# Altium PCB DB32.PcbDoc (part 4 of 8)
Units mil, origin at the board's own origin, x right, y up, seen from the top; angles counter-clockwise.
Board outline 3236.22 x 4456.69 mil, 8 copper layers (Top Layer, MidLayer1, MidLayer2, GND-Layer5, MidLayer3, VCC, MidLayer4, Bottom Layer), stack 61.8 mil thick; 207 components, 474 nets, 1777 pads, 1474 vias.
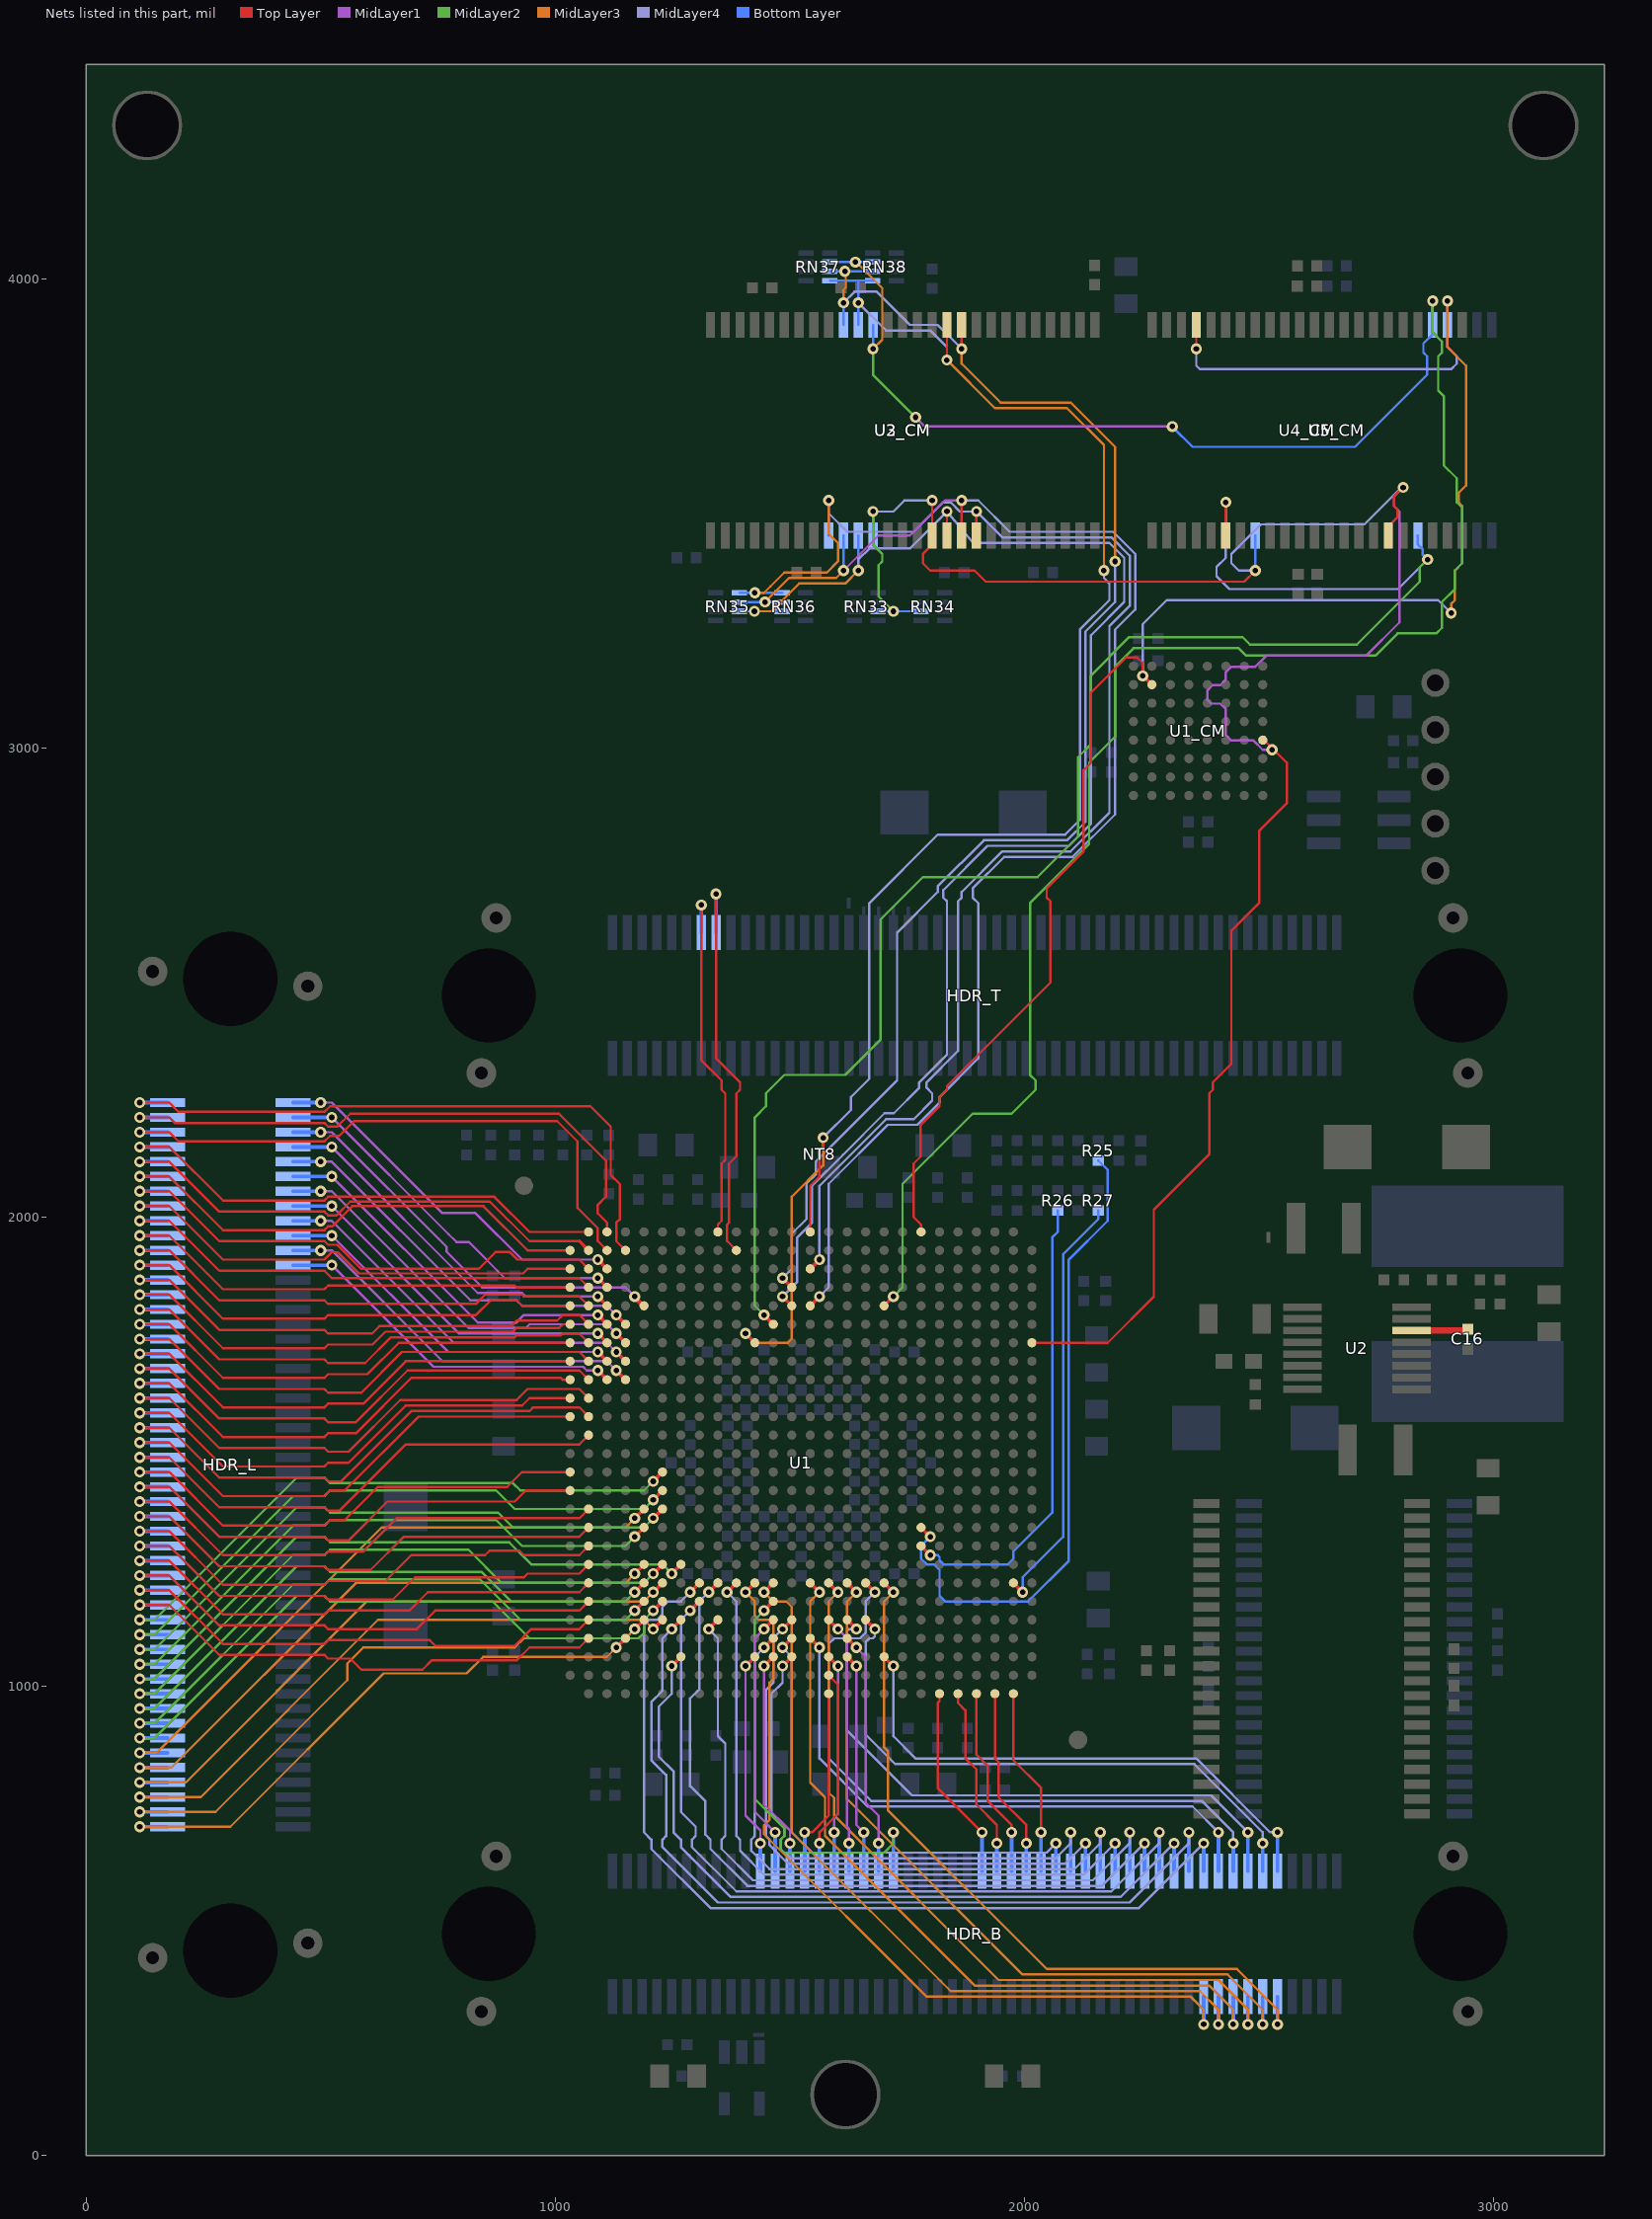
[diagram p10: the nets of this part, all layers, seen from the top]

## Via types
v1: diameter 23.62, hole 11.81, Top Layer to Bottom Layer, 839 vias
v2: diameter 23.62, hole 11.81, Top Layer to Bottom Layer, tented both sides, 499 vias
v3: diameter 27.56, hole 15.75, Top Layer to Bottom Layer, 135 vias
v4: diameter 23.62, hole 11.81, Top Layer to Bottom Layer, tented top, 1 vias

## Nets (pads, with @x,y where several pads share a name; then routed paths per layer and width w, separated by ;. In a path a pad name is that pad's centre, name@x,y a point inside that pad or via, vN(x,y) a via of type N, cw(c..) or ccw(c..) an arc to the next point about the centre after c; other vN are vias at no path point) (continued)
BUS_NBE3: RN37.6 RN38.7 U1.E18 U3_CM.39 U5_CM.40 | length 5006.7
  Top Layer w7.87: U1.E18@1700.79,1811.02 v1(1720.47,1830.71)
  MidLayer1 w5: v2(1767.72,3704.72) 1787.4,3685.04 v2(2314.96,3685.04)
  MidLayer2 w5: v2(1677.17,3850.39) 1677.17,3795.28 v2(1767.72,3704.72) ; v1(1720.47,1830.71) 1740.16,1850.39 1740.16,2031.5 1740.16,2039.37 1740.16,2070.86 1889.76,2220.47 1972.44,2220.47 2023.62,2271.65 2023.62,2291.34 2011.81,2303.15 2011.81,2669.29 2137.8,2795.28 2137.8,2968.5 2192.91,3023.62 2192.91,3173.23 2232.28,3212.6 2456.69,3212.6 2472.44,3196.85 2748.03,3196.85 2795.28,3244.1 2877.95,3244.1 2889.76,3255.91 2889.76,3311.02 2917.32,3338.58 2917.32,3377.95 2933.07,3393.7 2933.07,3511.81 2921.26,3523.62 2921.26,3574.8 2893.7,3602.36 2893.7,3750 2881.89,3761.81 2881.89,3834.65 2889.76,3842.52 2889.76,3866.14 2870.08,3885.83 v2(2870.08,3952.76)
  MidLayer3 w5: v1@1641.54,4035.43 1696.85,3980.12 1696.85,3870.08 v2(1677.17,3850.39)
  Bottom Layer w5: RN37.6@1586.22,4035.43 v1(1639.78,4035.43) RN38.7@1676.19,4035.43 RN38.7@1677.56,4035.43 ; v2(1677.17,3850.39) U3_CM.39@1677.17,3901.57 ; v2(2314.96,3685.04) 2358.27,3641.73 2704.72,3641.73 2858.27,3795.28 2858.27,3834.65 2850.39,3842.52 2850.39,3862.2 2870.08,3881.89 U5_CM.40@2870.08,3901.57 v2(2870.08,3952.76)
BUS_NOE: U1.A20 U1_CM.G2 U4_CM.41 U5_CM.41 | length 3868.3
  Top Layer w5: U1.A20@1779.53,1968.5 1779.53,1984.25 1763.78,2000 1763.78,2031.5 1763.78,2043.31 1763.78,2114.17 1778.54,2128.94 1778.54,2195.87 1818.9,2236.22 1818.9,2255.91 1834.64,2271.65 1834.64,2279.53 2055.12,2500 2055.12,2673.23 2047.24,2681.1 2047.24,2700.79 2125.98,2779.53 2125.98,2952.76 2141.73,2968.5 2141.73,3118.11 2216.54,3192.91 2240.16,3192.91 2251.97,3181.1 v1@2251.97,3154.53 ; v1@2255.91,3150.59 2255.91,3153.54 v1@2255.91,3154.53 ; v2(2366.14,3850.39) U4_CM.41@2366.14,3901.57
  Top Layer w7.87: v1@2251.97,3154.53 2252.46,3154.04 2255.91,3150.59 U1_CM.G2@2271.65,3134.84
  MidLayer3 w5: v2(2901.58,3952.76) 2901.57,3854.33 2940.94,3814.96 2940.94,3559.06 2925.2,3543.31 2925.2,3523.62 2933.07,3515.75 2933.07,3393.7 2917.32,3377.95 2917.32,3314.96 2909.45,3307.09 v1(2909.45,3287.4)
  MidLayer4 w5: v1(2251.97,3153.54) 2251.97,3263.78 2303.15,3314.96 2881.89,3314.96 v1(2909.45,3287.4) ; v2(2366.14,3850.39) 2366.14,3814.96 2374.02,3807.09 2909.45,3807.09 2921.26,3818.9 2921.26,3834.65 2901.58,3854.33 v2(2901.58,3952.76)
  Bottom Layer w5: U5_CM.41@2901.57,3901.57 v2(2901.58,3952.76)
BUS_NWE: RN33.7 RN34.6 U1.G26 U1_CM.A5 U2_CM.16 U3_CM.16 U4_CM.17 U5_CM.17 | length 4738.4
  Top Layer w5: U2_CM.16@1803.14,3452.75 v2(1803.14,3527.55) ; U2_CM.16@1803.15,3460.62 U2_CM.16@1803.15,3452.76 1803.15,3433.07 1783.46,3413.39 1783.46,3393.7 1799.21,3377.95 1893.7,3377.95 1917.32,3354.33 2468.5,3354.33 v1(2492.13,3377.95) ; U1.G26@2015.75,1732.28 2078.74,1732.28 2090.55,1732.28 2177.17,1732.28 2275.59,1830.71 2275.59,2015.75 2393.7,2133.86 2393.7,2263.78 2401.57,2271.65 2401.57,2287.4 2440.94,2326.77 2440.94,2610.24 2500,2669.29 2500,2822.83 2559.06,2881.89 2559.06,2968.5 2529.53,2998.03 2510.82,3016.74 U1_CM.A5@2507.87,3016.73 ; U4_CM.17@2775.59,3452.76 2775.59,3472.44 2795.28,3492.13 2795.28,3507.87 2787.4,3515.75 2787.4,3535.43 v1(2807.09,3555.12)
  MidLayer1 w5: v1(2527.56,2996.06) 2507.87,2996.06 2488.19,3015.75 2440.94,3015.75 2429.13,3027.56 2429.13,3082.68 2417.32,3094.49 2397.64,3094.49 2389.76,3102.36 2389.76,3122.05 2401.57,3133.86 2417.32,3133.86 2429.13,3145.67 2429.13,3161.42 2440.94,3173.23 2492.13,3173.23 2515.75,3196.85 2728.35,3196.85 2799.21,3267.72 2799.21,3503.94 2787.4,3515.75 2787.4,3535.43 v1(2807.09,3555.12)
  MidLayer2 w5: v2(1677.17,3503.94) 1677.17,3433.07 1696.85,3413.39 1696.85,3397.64 1688.98,3389.76 1688.98,3322.83 v1(1720.47,3291.34)
  MidLayer4 w5: v2(1677.17,3503.94) 1720.47,3503.94 1744.09,3527.55 v2(1803.14,3527.55) ; v1(2492.13,3377.95) 2456.69,3377.95 2440.94,3393.7 2440.94,3413.39 2503.94,3476.38 2724.41,3476.38 v1@2805.12,3557.09
  Bottom Layer w5: U3_CM.16@1677.17,3452.76 v2(1677.17,3503.94) ; RN33.7@1688.18,3291.34 v1(1720.47,3291.34) RN34.6@1779.53,3291.34 RN34.6@1779.92,3291.34 ; v1(2492.13,3377.95) U5_CM.17@2492.13,3452.76
BUS_SDRAM_CKE: RN37.7 RN38.6 U1.D13 U2_CM.37 U3_CM.37 | length 3199.4
  Top Layer w5: v2(1866.14,3850.39) U2_CM.37@1866.14,3901.57
  Top Layer w7.87: v1(1484.25,1870.08) U1.D13@1503.94,1850.39
  MidLayer3 w5: v2(1614.17,3948.82) 1614.17,3976.38 1618.9,3981.11 v1@1618.9,4015.75 ; v2(1866.14,3850.39) 1866.14,3818.9 1948.82,3736.22 2098.43,3736.22 2192.91,3641.73 v1(2192.91,3397.64)
  MidLayer4 w5: v1(1484.25,1870.08) 1503.94,1889.76 1503.94,1964.57 1535.43,1996.06 1535.43,2031.5 1535.43,2043.31 1535.43,2070.87 1555.12,2090.55 1555.12,2118.11 1728.35,2291.34 1728.35,2606.3 1814.96,2692.91 1814.96,2704.72 1913.39,2803.15 2090.55,2803.15 2129.92,2842.52 2129.92,3248.03 2192.91,3311.02 v1(2192.91,3397.64) ; v2(1614.17,3948.82) 1637.8,3972.44 1685.04,3972.44 1755.91,3901.57 1814.96,3901.57 v2(1866.14,3850.39)
  Bottom Layer w5: RN37.7@1586.22,4015.75 v1(1617.14,4015.75) RN38.6@1676.19,4015.75 RN38.6@1677.56,4015.75 ; U3_CM.37@1614.17,3901.57 v2(1614.17,3948.82)
BUS_SDRAM_CLK: NT8.2 RN37.8 RN38.5 U1.G11 U2_CM.38 U3_CM.38 | length 3444.5
  Top Layer w5: NT8.2@1562.99,2141.73 1570.87,2149.61 v1(1570.87,2169.29) ; v2(1834.64,3826.77) U2_CM.38@1834.65,3901.57
  Top Layer w7.87: v1(1405.51,1751.97) U1.G11@1425.2,1732.28
  MidLayer3 w5: v1(1405.51,1751.97) 1425.2,1732.28 1496.06,1732.28 1503.94,1740.16 1503.94,2043.31 1570.87,2110.24 v1(1570.87,2169.29) ; v2(1834.64,3826.77) 1937,3724.41 2090.55,3724.41 2169.29,3645.67 v1(2169.29,3377.95)
  MidLayer4 w5: v1(1570.87,2169.29) 1629.92,2228.35 1629.92,2255.91 1669.29,2295.28 1669.29,2669.29 1814.96,2814.96 2086.61,2814.96 2118.11,2846.46 2118.11,3251.97 2181.1,3314.96 2181.1,3350.39 2169.29,3362.2 v1(2169.29,3377.95) ; v2(1645.67,3948.82) 1704.72,3889.76 1799.21,3889.76 1834.64,3854.34 v2(1834.64,3826.77)
  Bottom Layer w5: RN37.8@1586.22,3996.06 RN38.5@1676.19,3996.06 RN38.5@1677.56,3996.06 ; U3_CM.38@1645.67,3901.57 v2(1645.67,3948.82) 1645.67,3996.06
BUS_SDRAM_FEEDBACK: NT8.1 U1.A14 | length 165.6
  Top Layer w5: U1.A14@1543.31,1968.5 1543.31,2066.93 1562.99,2086.61 NT8.1@1562.99,2125.98
BUS_SDRAM_NCAS: RN35.7 RN36.6 U1.E13 U2_CM.17 U3_CM.17 | length 3175.8
  Top Layer w5: U2_CM.17@1834.65,3452.76 1834.64,3499.99 v1(1834.65,3503.94)
  Top Layer w7.87: v1(1484.25,1830.71) U1.E13@1503.94,1811.02
  MidLayer3 w5: v1(1424.23,3291.34) 1460.63,3291.34 1519.68,3350.39 1618.11,3350.39 v2(1645.67,3377.95)
  MidLayer4 w5: v1(1484.25,1830.71) 1515.75,1862.2 1515.75,1956.69 1547.24,1988.19 1547.24,2031.5 1547.49,2043.31 1547.49,2067.18 1613.19,2132.87 1701.77,2221.46 1721.46,2221.46 1775.59,2275.59 1775.59,2287.4 1834.65,2346.46 1834.65,2673.23 1826.77,2681.1 1826.77,2696.85 1921.26,2791.34 2094.49,2791.34 2141.73,2838.58 2141.73,3240.16 2212.6,3311.02 2212.6,3405.51 2181.1,3437.01 1890.42,3437.01 v1(1834.65,3503.94) 1755.91,3425.2 1669.29,3425.2 1645.67,3401.57 v2(1645.67,3377.95)
  Bottom Layer w5: RN35.7@1393.3,3291.34 v1(1424.23,3291.34) RN36.6@1483.28,3291.34 RN36.6@1484.64,3291.34 ; v2(1645.67,3377.95) U3_CM.17@1645.67,3452.76
BUS_SDRAM_NCS: RN35.5 RN36.8 U1.C14 U2_CM.19 U3_CM.19 | length 3250.4
  Top Layer w5: U2_CM.19@1897.64,3452.76 v2(1897.63,3503.93)
  Top Layer w7.87: U1.C14@1543.31,1889.76 v1(1562.99,1909.45)
  MidLayer3 w5: v1(1425.2,3330.71) 1444.88,3330.71 1458.54,3344.36 1488.19,3374.02 1578.74,3374.02 1602.36,3397.64 1602.36,3437.01 1582.68,3456.69 v2(1582.68,3527.56)
  MidLayer4 w5: v1(1562.99,1909.45) 1562.99,2031.5 1562.99,2043.31 1562.99,2066.93 1704.72,2208.66 1763.78,2208.66 1803.15,2248.03 1803.15,2263.78 1791.34,2275.59 1791.34,2287.4 1858.27,2354.33 1858.27,2673.23 1866.14,2681.1 1866.14,2692.91 1952.76,2779.53 2098.43,2779.53 2181.1,2862.2 2181.1,3259.84 2224.41,3303.15 2224.41,3409.45 2185.04,3448.82 1952.76,3448.82 v2(1897.63,3503.93) 1862.21,3503.93 1842.52,3523.62 1826.77,3523.62 1763.78,3460.63 1622.05,3460.63 1582.68,3500 v2(1582.68,3527.56)
  Bottom Layer w5: RN35.5@1393.31,3330.71 v1(1425.2,3330.71) RN36.8@1483.28,3330.71 RN36.8@1484.26,3330.71 ; U3_CM.19@1582.68,3452.76 v2(1582.68,3527.56)
BUS_SDRAM_NRAS: RN35.6 RN36.7 U1.E14 U2_CM.18 U3_CM.18 | length 3197.5
  Top Layer w5: U2_CM.18@1866.14,3452.76 v1(1866.14,3527.55)
  Top Layer w7.87: U1.E14@1543.31,1811.02 v1(1562.99,1830.71)
  MidLayer1 w5: v2(1614.17,3377.95) 1688.98,3452.76 1755.91,3452.76 1830.7,3527.55 v1(1866.14,3527.55)
  MidLayer3 w5: v1(1446.86,3311.02) 1498.05,3362.2 1598.43,3362.2 v2(1614.17,3377.95)
  MidLayer4 w5: v1(1562.99,1830.71) 1582.68,1850.39 1582.68,2031.5 1582.68,2043.31 1582.68,2070.87 1708.66,2196.85 1771.65,2196.85 1818.9,2244.09 1818.9,2255.91 1901.57,2338.58 1901.57,2669.29 1889.76,2681.1 1889.76,2700.79 1956.69,2767.72 2102.36,2767.72 2192.91,2858.27 2192.91,3251.97 2236.22,3295.28 2236.22,3413.39 2188.98,3460.63 1968.5,3460.63 1901.58,3527.55 v1(1866.14,3527.55) v1@1858.27,3531.5
  Bottom Layer w5: RN35.6@1393.3,3311.02 v1(1446.86,3311.02) RN36.7@1483.28,3311.03 RN36.7@1484.64,3311.02 ; v2(1614.17,3377.95) U3_CM.18@1614.17,3452.76
BUS_SRAM_NCS: U1.F12 U4_CM.6 U5_CM.6 | length 3549.4
  Top Layer w5: U4_CM.6@2429.13,3452.76 2429.13,3503.94 v2(2429.13,3523.62)
  Top Layer w7.87: v1(1444.88,1791.34) U1.F12@1464.57,1771.65
  MidLayer2 w5: v1(1444.88,1791.34) 1425.2,1811.02 1425.2,2031.49 1425.2,2043.31 1425.2,2212.6 1448.82,2236.22 1448.82,2244.09 1448.82,2263.78 1488.19,2303.15 1618.11,2303.15 1692.91,2377.95 1692.91,2633.86 1783.46,2724.41 2027.56,2724.41 2114.17,2811.02 2114.17,2980.32 2141.73,3007.87 2141.73,3154.53 2223.42,3236.22 2464.57,3236.22 2480.32,3220.47 2708.66,3220.47 2842.52,3354.33 2842.52,3384.83 v2(2859.27,3401.57)
  MidLayer4 w5: v2(2429.13,3523.62) 2429.13,3405.51 2409.45,3385.83 2409.45,3366.14 2437.01,3338.58 2796.28,3338.58 v2(2859.27,3401.57)
  Bottom Layer w5: U5_CM.6@2838.58,3452.76 2838.58,3433.42 2848.92,3423.08 2848.92,3411.92 v2(2859.27,3401.57)
BUZZER: HDR_B.40 U1.AA12 | length 931.1
  Top Layer w7.87: v1(1444.88,1161.42) U1.AA12@1464.57,1181.1
  MidLayer2 w5: v1(1444.88,1161.42) 1425.2,1141.73 1425.2,921.26 1425.2,909.45 1425.2,759.84 1488.19,696.85 1488.19,681.1 1480.31,673.23 1480.31,653.54 1488.19,645.67 1700.79,645.67 1720.47,665.35 v2(1720.47,688.98)
  Bottom Layer w7.87: HDR_B.40@1720.48,606.3 v2(1720.47,688.98)
CAN_RXD: HDR_T.14 U1.A9 | length 783.6
  Top Layer w5: v2(1311.02,2665.35) 1311.02,2334.65 1354.33,2291.34 1354.33,2271.65 1362.2,2263.78 1362.2,2122.05 1354.33,2114.17 1354.33,2043.31 1354.33,2031.5 1354.33,1992.13 1346.46,1984.25 U1.A9@1346.46,1968.5
  Bottom Layer w7.87: HDR_T.14@1311.02,2606.3 v2(1311.02,2665.35)
CAN_TXD: HDR_T.16 U1.B10 | length 883.3
  Top Layer w5: v2(1342.52,2688.98) 1342.52,2338.58 1393.7,2287.4 1393.7,2271.65 1385.83,2263.78 1385.83,2129.92 1370.08,2114.17 1370.08,2043.31 1370.08,2031.5 1370.08,1988.19 1366.14,1984.25 1366.14,1948.82 U1.B10@1385.83,1929.13
  Bottom Layer w7.87: HDR_T.16@1342.52,2606.3 v2(1342.52,2688.98)
CCLK: R26.2 U1.V20 | length 1004.4
  Top Layer w7.87: U1.V20@1779.53,1299.21 v1(1799.21,1279.53)
  Bottom Layer w5: v1(1799.21,1279.53) 1814.96,1279.53 1818.9,1275.59 1818.9,1267.72 1826.77,1259.84 1964.57,1259.84 1976.38,1271.65 1976.38,1287.4 2059.06,1370.08 2059.06,1956.69 2070.86,1968.5 R26.2@2070.86,2014.25
COMP: C16.2 U2.6 | length 121.4
  Top Layer w13.78: U2.6@2824.58,1758.25 2942.3,1758.25 C16.2@2944.88,1760.82
DATA_DIN: R27.2 U1.Y25 | length 908.2
  Top Layer w7.87: U1.Y25@1976.38,1220.47 v1(1996.07,1200.79)
  Bottom Layer w5: v1(1996.07,1200.79) 1996.07,1232.29 2082.68,1318.9 2082.68,1921.26 2157.48,1996.06 R27.2@2157.48,2014.25
DAU_RESET_SW: HDR_B.38 U1.AC16 | length 523.8
  Top Layer w7.87: U1.AC16@1622.05,1102.36 v1(1641.73,1082.68)
  MidLayer1 w5: v1(1641.73,1082.68) 1661.42,1062.99 1661.42,921.26 1661.42,909.45 1661.42,751.97 1688.98,724.41 v2(1688.98,665.35)
  Bottom Layer w7.87: HDR_B.38@1688.98,606.3 v2(1688.98,665.35)
DAU_TFT_BLIGHT: HDR_B.91 U1.Y18 | length 1601.2
  Top Layer w7.87: U1.Y18@1700.79,1220.47 v1(1720.47,1200.79)
  MidLayer3 w5: v1(1720.47,1200.79) 1700.79,1181.1 1700.79,921.26 1700.79,909.45 1700.79,870.08 1708.66,862.2 1708.66,736.22 2047.24,397.64 2452.76,397.64 2539.37,311.02 v2(2539.37,279.53)
  Bottom Layer w7.87: v2(2539.37,279.53) HDR_B.91@2539.37,338.58
DAU_TFT_BLUE0: HDR_B.62 U1.AC13 | length 1077.8
  Top Layer w7.87: v1(1484.25,1082.68) U1.AC13@1503.94,1102.36
  MidLayer4 w5: v1(1484.25,1082.68) 1503.94,1062.99 1503.94,921.26 1503.94,909.45 1503.94,688.98 1547.24,645.67 2047.24,645.67 v2(2066.93,665.35)
  Bottom Layer w7.87: HDR_B.62@2066.93,606.3 v2(2066.93,665.35)
DAU_TFT_BLUE1: HDR_B.64 U1.AD13 | length 1187.7
  Top Layer w7.87: v1(1484.25,1043.31) U1.AD13@1503.94,1062.99
  MidLayer4 w5: v1(1484.25,1043.31) 1484.25,1007.87 1460.63,984.25 1460.63,921.26 1460.63,909.45 1460.63,728.35 1488.19,700.79 1488.19,681.1 1480.31,673.23 1480.31,653.54 1500,633.86 2066.93,633.86 2098.42,665.35 v2(2098.42,688.98)
  Bottom Layer w7.87: v2(2098.42,688.98) HDR_B.64@2098.43,606.3
DAU_TFT_BLUE2: HDR_B.66 U1.AB13 | length 1272.9
  Top Layer w7.87: v1(1484.25,1122.05) U1.AB13@1503.94,1141.73
  MidLayer4 w5: v1(1484.25,1122.05) 1464.57,1102.36 1464.57,1007.87 1448.82,992.13 1448.82,921.26 1448.82,909.45 1448.82,681.1 1456.69,673.23 1456.69,661.42 1496.06,622.05 2086.62,622.05 v2(2129.92,665.35)
  Bottom Layer w7.87: HDR_B.66@2129.92,606.3 v2(2129.92,665.35)
DAU_TFT_BLUE3: HDR_B.68 U1.AC12 | length 1361.9
  Top Layer w7.87: v1(1444.88,1082.68) U1.AC12@1464.57,1102.36
  MidLayer4 w5: v1(1444.88,1082.68) 1425.2,1062.99 1425.2,921.26 1425.2,909.45 1425.2,681.1 1417.32,673.23 1417.32,649.61 1456.69,610.24 2106.3,610.24 2161.42,665.35 v2(2161.42,688.98)
  Bottom Layer w7.87: HDR_B.68@2161.42,606.3 v2(2161.42,688.98)
DAU_TFT_BLUE4: HDR_B.70 U1.Y10 | length 1497.6
  Top Layer w7.87: v1(1366.14,1200.79) U1.Y10@1385.83,1220.47
  MidLayer4 w5: v1(1366.14,1200.79) 1385.83,1181.1 1385.83,921.26 1385.83,909.45 1385.83,681.1 1393.7,673.23 1393.7,649.61 1444.88,598.43 2125.98,598.43 v2(2192.91,665.35)
  Bottom Layer w7.87: HDR_B.70@2192.92,606.3 v2(2192.91,665.35)
DAU_TFT_CL1: HDR_B.88 U1.Y17 | length 1385.8
  Top Layer w7.87: U1.Y17@1661.42,1220.47 v1(1681.1,1200.79)
  MidLayer4 w5: v1(1681.1,1200.79) 1661.42,1181.1 1661.42,1114.17 1649.61,1102.36 1629.92,1102.36 1622.05,1094.49 1622.05,921.26 1622.05,909.45 1622.05,905.51 1759.84,767.72 2397.64,767.72 v2@2476.38,688.98
  Bottom Layer w7.87: HDR_B.88@2476.38,606.3 v2(2476.38,688.98)
DAU_TFT_CL2: HDR_B.90 U1.AB17 | length 1339.6
  Top Layer w7.87: U1.AB17@1661.42,1141.73 v1(1681.1,1122.05)
  MidLayer4 w5: v1(1681.1,1122.05) 1681.1,1106.3 1677.17,1102.36 1669.29,1102.36 1661.42,1094.49 1661.42,921.26 1661.42,909.45 1661.42,897.64 1724.41,834.65 2362.2,834.65 2507.87,688.98 v2(2507.87,665.35)
  Bottom Layer w7.87: v2(2507.87,665.35) HDR_B.90@2507.88,606.3 v2(2507.87,665.35)
DAU_TFT_CL3: HDR_B.92 U1.AD18 | length 1163.8
  Top Layer w7.87: U1.AD18@1700.79,1062.99 v1(1720.47,1043.31)
  MidLayer4 w5: v1(1720.47,1043.31) 1720.47,921.26 1720.47,909.45 1720.47,893.7 1767.72,846.46 2366.14,846.46 2523.62,688.98 v2(2539.37,688.98)
  Bottom Layer w7.87: HDR_B.92@2539.37,606.3 v2(2539.37,688.98)
DAU_TFT_DISP_ON: HDR_B.89 U1.Y16 | length 1639.2
  Top Layer w7.87: U1.Y16@1622.05,1220.47 v1(1641.73,1200.79)
  MidLayer3 w5: v1(1641.73,1200.79) 1622.05,1181.1 1622.05,921.26 1622.05,909.45 1622.05,759.84 1996.06,385.83 2433.07,385.83 2507.87,311.02 v2(2507.88,279.53)
  Bottom Layer w7.87: v2(2507.88,279.53) HDR_B.89@2507.88,338.58
DAU_TFT_GREEN0: HDR_B.72 U1.AB9 | length 1551
  Top Layer w7.87: v1(1326.77,1122.05) U1.AB9@1346.46,1141.73
  MidLayer4 w5: v1(1326.77,1122.05) 1346.46,1102.36 1346.46,921.26 1346.46,909.45 1346.46,893.7 1362.2,877.95 1362.2,681.1 1354.33,673.23 1354.33,653.54 1421.26,586.61 2145.67,586.61 2224.41,665.36 v2(2224.41,688.98)
  Bottom Layer w7.87: HDR_B.72@2224.41,606.3 v2(2224.41,688.98)
DAU_TFT_GREEN1: HDR_B.74 U1.Y9 | length 1663.7
  Top Layer w7.87: v1(1326.77,1200.79) U1.Y9@1346.46,1220.47
  MidLayer4 w5: v1(1326.77,1200.79) 1307.09,1181.1 1307.09,994.09 1287.4,974.41 1287.4,921.26 1287.4,909.45 1287.4,787.4 1319.88,754.92 1319.88,684.06 1330.71,673.23 1330.71,653.54 1409.45,574.8 2165.35,574.8 v2(2255.9,665.35)
  Bottom Layer w7.87: HDR_B.74@2255.91,606.3 v2(2255.9,665.35)
DAU_TFT_GREEN2: HDR_B.76 U1.AA8 | length 1740.1
  Top Layer w7.87: v1(1287.4,1161.42) U1.AA8@1307.09,1181.1
  MidLayer4 w5: v1(1287.4,1161.42) 1267.72,1141.73 1267.72,921.26 1267.72,909.45 1267.72,732.28 1299.21,700.79 1299.21,681.1 1291.34,673.23 1291.34,657.48 1385.83,562.99 2185.04,562.99 2287.4,665.35 v2(2287.4,688.98)
  Bottom Layer w7.87: HDR_B.76@2287.41,606.3 v2(2287.4,688.98)
DAU_TFT_GREEN3: HDR_B.78 U1.AD7 | length 1646.2
  Top Layer w7.87: v1(1248.03,1043.31) U1.AD7@1267.72,1062.99
  MidLayer4 w5: v1(1248.03,1043.31) 1248.03,984.25 1220.47,956.69 1220.47,921.26 1220.47,909.45 1220.47,850.39 1251.97,818.9 1251.97,688.98 1267.72,673.23 1267.72,657.48 1374.02,551.18 2204.72,551.18 v2(2318.9,665.35)
  Bottom Layer w7.87: HDR_B.78@2318.9,606.3 v2(2318.9,665.35)
DAU_TFT_GREEN4: HDR_B.80 U1.AB7 | length 1856.1
  Top Layer w7.87: v1(1248.03,1122.05) U1.AB7@1267.72,1141.73
  MidLayer4 w5: v1(1248.03,1122.05) 1228.35,1102.36 1228.35,990.16 1204.72,966.53 1204.72,921.26 1204.72,909.45 1204.72,842.52 1236.22,811.02 1236.22,681.1 1228.35,673.23 1228.35,657.48 1346.46,539.37 2224.41,539.37 2350.39,665.35 v2(2350.39,688.98)
  Bottom Layer w7.87: HDR_B.80@2350.4,606.3 v2(2350.39,688.98)
DAU_TFT_GREEN5: HDR_B.82 U1.Y8 | length 1993.2
  Top Layer w7.87: v1(1287.4,1200.79) U1.Y8@1307.09,1220.47
  MidLayer4 w5: v1(1287.4,1200.79) 1267.72,1181.1 1240.16,1181.1 1228.35,1169.29 1228.35,1153.54 1216.54,1141.73 1200.79,1141.73 1188.98,1129.92 1188.98,921.26 1188.98,909.45 1188.98,688.98 1204.72,673.23 1204.72,653.54 1330.71,527.56 2244.09,527.56 v2(2381.89,665.35)
  Bottom Layer w7.87: HDR_B.82@2381.89,606.3 v2(2381.89,665.35)
DAU_TFT_IRQ: HDR_B.81 U1.Y11 | length 1772.5
  Top Layer w7.87: v1(1405.51,1200.79) U1.Y11@1425.2,1220.47
  MidLayer3 w5: v1(1405.51,1200.79) 1425.2,1181.1 1425.2,1149.61 1433.07,1141.73 1456.69,1141.73 1464.57,1133.86 1464.57,1015.75 1456.69,1007.87 1456.69,921.26 1456.69,909.45 1456.69,715.55 1444.88,703.74 1444.88,685.04 1791.34,338.58 2354.33,338.58 2381.89,311.02 v2(2381.89,279.53)
  Bottom Layer w7.87: v2(2381.89,279.53) HDR_B.81@2381.89,338.58
DAU_TFT_M: HDR_B.87 U1.Y15 | length 1660.9
  Top Layer w7.87: U1.Y15@1582.68,1220.47 v1(1602.36,1200.79)
  MidLayer3 w5: v1(1602.36,1200.79) 1582.68,1181.1 1582.68,921.26 1582.68,909.45 1582.68,773.62 1594.49,761.81 1594.49,724.41 1944.88,374.02 2413.39,374.02 2476.38,311.02 v2(2476.38,279.53)
  Bottom Layer w7.87: v2(2476.38,279.53) HDR_B.87@2476.38,338.58
DAU_TFT_MUX: HDR_B.85 U1.Y14 | length 1682.7
  Top Layer w7.87: U1.Y14@1543.31,1220.47 v1(1562.99,1200.79)
  MidLayer3 w5: v1(1562.99,1200.79) 1543.31,1181.1 1543.31,921.26 1543.31,909.45 1543.31,795.28 1574.8,763.78 1574.8,681.1 1893.7,362.2 2393.7,362.2 2444.88,311.02 v2(2444.88,279.53)
  Bottom Layer w7.87: v2(2444.88,279.53) HDR_B.85@2444.89,338.58
DAU_TFT_POL: HDR_B.83 U1.Y12 | length 1736.8
  Top Layer w7.87: v1(1444.88,1200.79) U1.Y12@1464.57,1220.47
  MidLayer3 w5: v1(1444.88,1200.79) 1464.57,1181.1 1492.12,1181.1 1503.93,1169.29 1503.93,921.26 1503.94,909.45 1503.94,688.98 1842.52,350.39 2374.02,350.39 2413.39,311.03 v2(2413.39,279.53)
  Bottom Layer w7.87: v2(2413.39,279.53) HDR_B.83@2413.39,338.58
DAU_TFT_RED0: HDR_B.52 U1.AF21 | length 420.7
  Top Layer w5: U1.AF21@1814.96,984.25 1816.93,982.28 1818.9,980.32 1818.9,968.5 1814.96,964.57 1814.96,921.26 1814.96,910.43 1814.96,783.22 v2@1909.33,688.85 ; v2@1909.45,688.73 v2(1909.45,688.98)
  Bottom Layer w7.87: HDR_B.52@1909.45,606.3 v2(1909.45,688.98)
DAU_TFT_RED1: HDR_B.54 U1.AF22 | length 412.2
  Top Layer w5: U1.AF22@1858.27,984.25 1858.27,964.57 1874.02,948.82 1874.02,921.26 1874.02,909.45 1874.02,846.46 1897.64,822.83 1897.64,748.03 1940.94,704.73 v2(1940.94,665.35)
  Bottom Layer w7.87: HDR_B.54@1940.95,606.3 v2(1940.94,665.35)
DAU_TFT_RED2: HDR_B.56 U1.AF23 | length 408.9
  Top Layer w5: U1.AF23@1897.64,984.25 1897.64,921.26 1897.64,909.45 1897.64,854.33 1921.26,830.71 1921.26,755.91 1972.44,704.73 v2(1972.44,688.98)
  Bottom Layer w7.87: HDR_B.56@1972.44,606.3 v2(1972.44,688.98)
DAU_TFT_RED3: HDR_B.58 U1.AF24 | length 405.7
  Top Layer w5: U1.AF24@1937.01,984.25 1937.01,921.26 1937.01,909.45 1937.01,846.46 1944.88,838.58 1944.88,763.78 2003.94,704.73 v2(2003.94,665.35)
  Bottom Layer w7.87: HDR_B.58@2003.94,606.3 v2(2003.94,665.35)
DAU_TFT_RED4: HDR_B.60 U1.AF25 | length 402.4
  Top Layer w5: U1.AF25@1976.38,984.25 1976.38,921.26 1976.38,909.45 1976.38,842.52 2035.43,783.47 v2(2035.43,688.98)
  Bottom Layer w7.87: HDR_B.60@2035.44,606.3 v2(2035.43,688.98)
DAU_TFT_STH: HDR_B.86 U1.AB16 | length 1358.8
  Top Layer w7.87: U1.AB16@1622.05,1141.73 v1(1641.73,1122.05)
  MidLayer4 w5: v1(1641.73,1122.05) 1625.98,1122.05 1622.05,1118.11 1622.05,1110.24 1614.17,1102.36 1594.49,1102.36 1582.68,1090.55 1582.68,921.26 1582.68,909.45 1582.68,846.46 1673.23,755.91 2377.95,755.91 2444.88,688.98 v2(2444.88,665.35)
  Bottom Layer w7.87: HDR_B.86@2444.89,606.3 v2(2444.88,665.35)
DAU_TFT_STV: HDR_B.84 U1.AC14 | length 1262.4
  Top Layer w7.87: U1.AC14@1543.31,1102.36 v1(1562.99,1082.68)
  MidLayer4 w5: v1(1562.99,1082.68) 1562.99,921.26 1562.99,909.45 1562.99,846.46 1665.35,744.09 2358.27,744.09 v2@2413.38,688.98
  Bottom Layer w7.87: HDR_B.84@2413.39,606.3 v2(2413.38,688.98)
DIP0: HDR_B.22 U1.AD11 | length 477.9
  Top Layer w7.87: v1(1405.51,1043.31) U1.AD11@1425.2,1062.99
  MidLayer1 w5: v1(1405.51,1043.31) 1405.51,921.26 1405.51,909.45 1405.51,724.41 1437.01,692.91 v2(1437.01,665.35)
  Bottom Layer w7.87: HDR_B.22@1437.01,606.3 v2(1437.01,665.35)
DIP1: HDR_B.24 U1.AB12 | length 569.7
  Top Layer w7.87: v1(1444.88,1122.05) U1.AB12@1464.57,1141.73
  MidLayer1 w5: v1(1444.88,1122.05) 1425.2,1102.36 1425.2,921.26 1425.2,909.45 1425.2,732.28 v2(1468.5,688.98)
  Bottom Layer w7.87: HDR_B.24@1468.51,606.3 v2(1468.5,688.98)
DIP2: HDR_B.26 U1.AD12 | length 487.7
  Top Layer w7.87: v1(1444.88,1043.31) U1.AD12@1464.57,1062.99
  MidLayer1 w5: v1(1444.88,1043.31) 1444.88,921.26 1444.88,909.45 1444.88,748.03 1500,692.91 v2(1500,665.35)
  Bottom Layer w7.87: HDR_B.26@1500,606.3 v2(1500,665.35)
DIP3: HDR_B.28 U1.AF15 | length 412.3
  Top Layer w5: v2@1527.56,688.98 v2(1531.5,688.98) 1547.24,688.98 1582.68,724.41 1582.68,909.45 1582.68,921.26 U1.AF15@1582.68,984.25
  Bottom Layer w7.87: HDR_B.28@1531.5,606.3 v2(1531.5,688.98)
DIP4: HDR_B.30 U1.AE15 | length 441.8
  Top Layer w5: v2(1562.99,665.35) 1562.99,688.98 1602.36,728.35 1602.36,909.45 1602.36,921.26 1602.36,1003.93 U1.AE15@1582.68,1023.62
  Bottom Layer w7.87: HDR_B.30@1562.99,606.3 v2(1562.99,665.35)
DIP5: HDR_B.32 U1.AD15 | length 468.1
  Top Layer w7.87: U1.AD15@1582.68,1062.99 v1(1602.36,1043.31)
  MidLayer1 w5: v2(1594.49,688.98) 1594.49,720.47 1602.36,728.35 1602.36,909.45 1602.36,921.26 v1(1602.36,1043.31)
  Bottom Layer w7.87: HDR_B.32@1594.49,606.3 v2(1594.49,688.98)
DIP6: HDR_B.34 U1.AB15 | length 553.4
  Top Layer w7.87: U1.AB15@1582.68,1141.73 v1(1602.36,1122.05)
  MidLayer1 w5: v1(1602.36,1122.05) 1622.05,1102.36 1622.05,921.26 1622.05,909.45 1622.05,700.79 1625.98,696.85 v2(1625.98,665.35)
  Bottom Layer w7.87: HDR_B.34@1625.99,606.3 v2(1625.98,665.35)
DIP7: HDR_B.36 U1.AD16 | length 471.4
  Top Layer w7.87: U1.AD16@1622.05,1062.99 v1(1641.73,1043.31)
  MidLayer1 w5: v1(1641.73,1043.31) 1641.74,921.26 1641.73,909.45 1641.73,704.72 v2(1657.48,688.98)
  Bottom Layer w7.87: HDR_B.36@1657.48,606.3 v2(1657.48,688.98)
DONE: R25.2 U1.U20 | length 1399.1
  Top Layer w7.87: U1.U20@1779.53,1338.58 v1(1799.21,1318.9)
  Bottom Layer w5: v1(1799.21,1318.9) 1779.53,1299.21 1779.53,1271.65 1791.34,1259.84 1807.09,1259.84 1818.9,1248.03 1818.9,1192.91 1830.71,1181.1 2007.87,1181.1 2094.49,1267.72 2094.49,1909.45 2177.17,1992.13 2177.17,2100.86 R25.2@2157.48,2120.55
EXTEND_A0: HDR_L.1 U1.B4 | length 1400.9
  Top Layer w5: v2(114.17,2244.09) 177.17,2244.09 196.85,2224.41 409.45,2224.41 ; 385.83,2224.41 507.88,2224.41 519.69,2236.22 1074.8,2236.22 1118.11,2192.91 1118.11,2089.57 1137.8,2069.88 1137.8,2043.31 1137.8,2031.49 1137.8,1996.06 1129.92,1988.19 1129.92,1948.82 U1.B4@1149.61,1929.13
  Bottom Layer w7.87: v2(114.17,2244.09) HDR_L.1@173.23,2244.09
EXTEND_A1: HDR_L.3 U1.A3 | length 1328.5
  Top Layer w5: v2(114.17,2212.6) 153.54,2212.6 ; 137.8,2212.6 177.17,2212.6 188.98,2200.79 409.45,2200.79 ; 377.95,2200.79 507.88,2200.79 515.75,2192.91 535.43,2192.91 562.99,2220.47 1007.87,2220.47 1108.11,2120.24 1108.11,2043.96 1090.55,2026.4 1090.55,2007.87 1110.24,1988.19 U1.A3@1110.24,1968.5
  Bottom Layer w7.87: v2(114.17,2212.6) HDR_L.3@173.23,2212.6
EXTEND_A2: HDR_L.5 U1.B3 | length 1314.2
  Top Layer w5: v2(114.17,2181.1) 157.48,2181.1 ; 137.8,2181.1 177.17,2181.1 196.85,2161.42 507.88,2161.42 519.69,2173.23 539.37,2173.23 570.87,2204.72 1003.94,2204.72 1047.24,2161.42 1047.24,2043.31 1047.24,2031.5 1047.24,2019.68 1090.55,1976.38 1090.55,1948.82 U1.B3@1110.24,1929.13
  Bottom Layer w7.87: v2(114.17,2181.1) HDR_L.5@173.23,2181.1
EXTEND_A3: HDR_L.7 U1.A2 | length 1129.7
  Top Layer w5: v2(114.17,2149.61) 153.54,2149.61 ; 137.8,2149.61 177.17,2149.61 ; 188.98,2137.8 177.17,2149.61 ; U1.A2@1070.87,1968.5 968.5,1968.5 956.69,1968.5 944.88,1968.5 870.08,2043.31 515.75,2043.31 507.87,2035.43 291.34,2035.43 177.16,2149.61
  Bottom Layer w7.87: v2(114.17,2149.61) HDR_L.7@173.23,2149.6
EXTEND_A4: HDR_L.9 U1.B2 | length 1185.8
  Top Layer w5: v2(114.17,2118.11) 149.6,2118.11 ; 137.8,2118.11 177.17,2118.11 ; 196.85,2098.43 177.17,2118.11 ; U1.B2@1070.87,1929.13 1051.18,1948.82 968.5,1948.82 956.69,1948.82 944.88,1948.82 860.39,2033.31 563.16,2033.31 533.79,2003.94 515.75,2003.94 507.87,2011.81 283.46,2011.81 177.16,2118.11
  Top Layer w7.87: 1051.18,1948.82 U1.B2@1070.87,1929.13
  Bottom Layer w7.87: v2(114.17,2118.11) HDR_L.9@173.23,2118.11
EXTEND_A5: HDR_L.11 U1.B1 | length 1112.3
  Top Layer w5: v2(114.17,2086.62) 149.61,2086.62 ; 137.8,2086.61 177.17,2086.61 ; 188.98,2074.8 177.17,2086.61 ; U1.B1@1031.5,1929.13 968.5,1929.13 956.69,1929.13 940.94,1929.13 846.77,2023.31 567.3,2023.31 524.31,1980.31 515.75,1980.31 507.87,1972.44 291.34,1972.44 177.16,2086.61
  Bottom Layer w7.87: v2(114.17,2086.62) HDR_L.11@173.23,2086.61
EXTEND_A6: HDR_L.13 U1.C2 | length 1153.3
  Top Layer w5: v2(114.17,2055.12) 149.61,2055.12 ; 137.8,2055.12 177.16,2055.12 ; 196.85,2035.43 177.17,2055.12 ; U1.C2@1070.87,1889.76 1051.18,1909.45 968.5,1909.45 956.69,1909.45 919.24,1909.45 903.16,1925.54 872.34,1925.54 836.88,1890.08 585.64,1890.08 534.77,1940.94 515.75,1940.94 507.87,1948.82 283.46,1948.82 177.16,2055.12
  Bottom Layer w7.87: v2(114.17,2055.12) HDR_L.13@173.23,2055.12
EXTEND_A7: HDR_L.15 U1.C1 | length 1064.7
  Top Layer w5: v2(114.17,2023.62) 149.61,2023.62 ; 137.8,2023.62 177.16,2023.62 291.34,1909.45 507.87,1909.45 523.62,1925.2 536.38,1925.2 581.5,1880.08 931.26,1880.08 940.94,1889.77 956.69,1889.77 968.5,1889.76 U1.C1@1031.5,1889.76
  Bottom Layer w7.87: v2(114.17,2023.62) HDR_L.15@173.23,2023.62
EXTEND_A8: HDR_L.17 U1.D2 | length 1090.4
  Top Layer w5: v2(114.17,1992.13) 149.61,1992.13 ; 137.8,1992.13 177.16,1992.13 283.46,1885.83 507.87,1885.83 523.62,1870.08 960.83,1870.08 ; 956.69,1870.08 968.5,1870.08 1051.18,1870.08 U1.D2@1070.87,1850.39
  Bottom Layer w7.87: v2(114.17,1992.13) HDR_L.17@173.23,1992.12
EXTEND_A9: HDR_L.19 U1.D1 | length 1040.4
  Top Layer w5: v2(114.17,1960.63) 149.61,1960.63 ; 137.8,1960.63 177.16,1960.63 291.34,1846.46 507.87,1846.46 515.75,1854.33 913.39,1854.33 917.32,1850.39 956.69,1850.39 968.5,1850.39 U1.D1@1031.5,1850.39
  Bottom Layer w7.87: v2(114.17,1960.63) HDR_L.19@173.23,1960.63
EXTEND_A10: HDR_L.21 U1.E2 | length 1092.8
  Top Layer w5: v2(114.17,1929.13) 149.61,1929.13 ; 137.8,1929.13 177.16,1929.13 283.46,1822.83 507.87,1822.83 515.75,1814.96 830.71,1814.96 850.39,1834.65 929.13,1834.65 933.07,1830.71 956.69,1830.71 968.5,1830.71 1051.18,1830.71 U1.E2@1070.87,1811.02
  Bottom Layer w7.87: v2(114.17,1929.13) HDR_L.21@173.23,1929.13
EXTEND_A11: HDR_L.23 U1.E1 | length 1056.7
  Top Layer w5: v2(114.17,1897.64) 149.61,1897.64 ; 137.8,1897.64 177.16,1897.64 291.34,1783.46 507.87,1783.46 515.75,1791.34 830.71,1791.34 862.2,1822.83 917.32,1822.83 929.13,1811.02 956.69,1811.02 968.5,1811.02 U1.E1@1031.5,1811.02
  Bottom Layer w7.87: v2(114.17,1897.64) HDR_L.23@173.23,1897.64
EXTEND_A12: HDR_L.25 U1.F2 | length 1099.3
  Top Layer w5: v2(114.17,1866.14) 149.61,1866.14 ; 137.8,1866.14 177.16,1866.14 283.46,1759.84 507.87,1759.84 515.75,1751.97 609.25,1751.97 625,1767.72 905.51,1767.72 917.32,1779.53 956.69,1779.53 968.5,1779.53 1003.94,1779.53 1015.75,1791.34 1051.18,1791.34 U1.F2@1070.87,1771.65
  Bottom Layer w7.87: v2(114.17,1866.14) HDR_L.25@173.23,1866.14
EXTEND_A13: HDR_L.27 U1.F1 | length 1056.7
  Top Layer w5: v2(114.17,1834.65) 149.61,1834.65 ; 137.8,1834.65 177.16,1834.65 291.34,1720.47 507.87,1720.47 515.75,1728.35 610.24,1728.35 637.8,1755.91 909.45,1755.91 917.32,1763.78 956.69,1763.78 968.5,1763.78 1007.87,1763.78 1015.75,1771.65 U1.F1@1031.5,1771.65
  Bottom Layer w7.87: v2(114.17,1834.65) HDR_L.27@173.23,1834.64
EXTEND_A14: HDR_L.29 U1.G2 | length 1105.2
  Top Layer w5: v2(114.17,1803.15) 145.67,1803.15 ; 137.8,1803.15 177.16,1803.15 283.46,1696.85 507.87,1696.85 515.75,1688.98 594.49,1688.98 649.61,1744.09 913.39,1744.09 917.32,1748.03 956.69,1748.03 968.5,1748.03 1011.81,1748.03 1015.75,1751.97 1051.18,1751.97 U1.G2@1070.87,1732.28
  Bottom Layer w7.87: v2(114.17,1803.15) HDR_L.29@173.23,1803.15
EXTEND_A15: HDR_L.31 U1.G1 | length 1062.5
  Top Layer w5: v2(114.17,1771.65) 145.67,1771.65 ; 137.8,1771.65 177.16,1771.65 291.34,1657.48 507.87,1657.48 515.75,1665.35 599.41,1665.35 666.34,1732.28 956.69,1732.28 968.5,1732.28 U1.G1@1031.5,1732.28
  Bottom Layer w7.87: v2(114.17,1771.65) HDR_L.31@173.23,1771.65
EXTEND_A16: HDR_L.33 U1.H2 | length 1114.9
  Top Layer w5: v2(114.17,1740.16) 145.67,1740.16 ; 137.8,1740.16 177.16,1740.16 283.46,1633.86 507.87,1633.86 515.75,1625.98 586.61,1625.98 673.23,1712.6 956.69,1712.6 968.5,1712.6 1019.68,1712.6 1051.18,1712.6 U1.H2@1070.87,1692.91
  Bottom Layer w7.87: v2(114.17,1740.16) HDR_L.33@173.23,1740.15
EXTEND_A17: HDR_L.35 U1.H1 | length 1076.3
  Top Layer w5: v2(114.17,1708.66) 149.61,1708.66 ; 137.8,1708.66 177.16,1708.66 291.34,1594.49 507.87,1594.49 515.75,1602.36 590.55,1602.36 681.1,1692.91 956.69,1692.91 968.5,1692.91 U1.H1@1031.5,1692.91
  Bottom Layer w7.87: v2(114.17,1708.66) HDR_L.35@173.23,1708.66
EXTEND_A18: HDR_L.37 U1.J2 | length 1128.7
  Top Layer w5: v2(114.17,1677.17) 149.61,1677.17 ; 137.8,1677.17 177.16,1677.17 283.46,1570.86 507.87,1570.86 515.75,1562.99 574.8,1562.99 685.04,1673.23 956.69,1673.23 968.5,1673.23 1051.18,1673.23 U1.J2@1070.87,1653.54
  Bottom Layer w7.87: v2(114.17,1677.17) HDR_L.37@173.23,1677.16
EXTEND_A19: HDR_L.39 U1.J1 | length 1089.3
  Top Layer w5: v2(114.17,1645.67) 149.61,1645.67 ; 137.8,1645.67 177.16,1645.67 291.34,1531.49 507.87,1531.49 515.75,1539.37 574.8,1539.37 692.91,1657.48 956.69,1657.48 968.5,1657.48 1011.81,1657.48 1015.75,1653.54 U1.J1@1031.5,1653.54
  Bottom Layer w7.87: v2(114.17,1645.67) HDR_L.39@173.23,1645.67
EXTEND_A20: HDR_L.41 U1.K2 | length 1138.4
  Top Layer w5: v2(114.17,1614.17) 149.61,1614.17 ; 137.8,1614.17 177.16,1614.17 283.46,1507.87 507.87,1507.87 515.75,1500 559.05,1500 669.29,1610.24 917.32,1610.24 940.94,1633.86 956.69,1633.86 968.5,1633.86 1051.18,1633.86 U1.K2@1070.87,1614.17
  Bottom Layer w7.87: v2(114.17,1614.17) HDR_L.41@173.23,1614.17
EXTEND_A21: HDR_L.43 U1.K1 | length 1095.8
  Top Layer w5: v2(114.17,1582.68) 149.61,1582.68 ; 137.8,1582.68 177.16,1582.68 291.34,1468.5 507.87,1468.5 515.75,1476.38 559.05,1476.38 681.1,1598.43 929.13,1598.43 944.88,1614.17 956.69,1614.17 968.5,1614.17 U1.K1@1031.5,1614.17
  Bottom Layer w7.87: v2(114.17,1582.68) HDR_L.43@173.23,1582.67
EXTEND_A22: HDR_L.45 U1.L2 | length 1136.4
  Top Layer w5: v2(114.17,1551.18) 177.16,1551.18 283.46,1444.88 507.87,1444.88 515.75,1437.01 543.31,1437.01 692.91,1586.61 944.88,1586.61 952.76,1594.49 956.69,1594.49 968.5,1594.49 1051.18,1594.49 U1.L2@1070.87,1574.8
  Bottom Layer w7.87: v2(114.17,1551.18) HDR_L.45@173.23,1551.18
EXTEND_A23: HDR_L.47 U1.L1 | length 1093.8
  Top Layer w5: v2(114.17,1519.69) 177.16,1519.69 291.34,1405.51 507.87,1405.51 519.68,1417.32 551.18,1417.32 708.66,1574.8 956.69,1574.8 968.5,1574.8 U1.L1@1031.5,1574.8
  Bottom Layer w7.87: v2(114.17,1519.69) HDR_L.47@173.23,1519.68
EXTEND_A24: HDR_L.49 U1.M2 | length 1129.9
  Top Layer w5: v2(114.17,1488.19) 177.16,1488.19 283.46,1381.89 507.87,1381.89 515.75,1374.01 539.37,1374.01 681.1,1515.75 956.69,1515.75 968.5,1515.75 1051.18,1515.75 U1.M2@1070.87,1535.43
  Bottom Layer w7.87: v2(114.17,1488.19) HDR_L.49@173.23,1488.19
EXTEND_A25: HDR_L.51 U1.P1 | length 1071
  Top Layer w5: v2(114.17,1456.69) 177.16,1456.69 291.34,1342.52 507.87,1342.52 519.68,1354.33 551.18,1354.33 622.05,1425.2 897.64,1425.2 929.13,1456.69 956.69,1456.69 968.5,1456.69 U1.P1@1031.5,1456.69
  Bottom Layer w7.87: v2(114.17,1456.69) HDR_L.51@173.23,1456.69
EXTEND_A26: HDR_L.53 U1.R1 | length 1067.7
  Top Layer w5: v2(114.17,1425.2) 177.16,1425.2 283.46,1318.9 507.87,1318.9 515.75,1311.02 559.05,1311.02 641.73,1393.7 913.39,1393.7 937.01,1417.32 956.69,1417.32 968.5,1417.32 U1.R1@1031.5,1417.32
  Bottom Layer w7.87: v2(114.17,1425.2) HDR_L.53@173.23,1425.19
EXTEND_A27: HDR_L.55 U1.T2 | length 1103.8
  Top Layer w5: v2(114.17,1393.7) 177.16,1393.7 291.34,1279.53 507.87,1279.53 515.75,1287.4 590.55,1287.4 661.42,1358.27 956.69,1358.27 968.5,1358.27 1051.18,1358.27 U1.T2@1070.87,1377.95
  Bottom Layer w7.87: v2(114.17,1393.7) HDR_L.55@173.23,1393.7
EXTEND_A28: HDR_L.57 U1.U2 | length 1100.5
  Top Layer w5: v2(114.17,1362.21) 177.16,1362.21 283.46,1255.9 507.87,1255.9 515.75,1248.03 606.3,1248.03 677.17,1318.9 956.69,1318.9 968.51,1318.9 1051.18,1318.9 U1.U2@1070.87,1338.58
  Bottom Layer w7.87: v2(114.17,1362.21) HDR_L.57@173.23,1362.2
EXTEND_A29: HDR_L.59 U1.V2 | length 1105.2
  Top Layer w5: v2(114.17,1330.71) 177.16,1330.71 291.34,1216.54 507.87,1216.54 515.75,1224.41 637.8,1224.41 692.91,1279.53 850.39,1279.53 859.99,1289.12 923.47,1289.12 933.07,1279.53 956.69,1279.53 968.51,1279.53 1051.18,1279.53 U1.V2@1070.87,1299.21
  Bottom Layer w7.87: v2(114.17,1330.71) HDR_L.59@173.23,1330.71
EXTEND_A30: HDR_L.61 U1.W2 | length 1094
  Top Layer w5: v2(114.17,1299.21) 177.16,1299.21 283.46,1192.91 507.87,1192.91 515.75,1185.04 653.54,1185.04 700.79,1232.28 933.07,1232.28 940.95,1240.16 956.69,1240.16 968.51,1240.16 1051.18,1240.16 U1.W2@1070.87,1259.84
  Bottom Layer w7.87: v2(114.17,1299.21) HDR_L.61@173.23,1299.21
EXTEND_A31: HDR_L.63 U1.Y2 | length 1090.8
  Top Layer w5: v2(114.17,1267.72) 177.16,1267.72 291.34,1153.54 507.87,1153.54 515.75,1161.42 688.98,1161.42 728.35,1200.79 956.69,1200.79 968.5,1200.79 1051.18,1200.79 U1.Y2@1070.87,1220.47
  Bottom Layer w7.87: v2(114.17,1267.72) HDR_L.63@173.23,1267.71
EXTEND_A32: HDR_L.65 U1.AA2 | length 1087.5
  Top Layer w5: v2(114.17,1236.22) 177.16,1236.22 283.46,1129.92 507.87,1129.92 515.75,1122.05 704.72,1122.05 744.09,1161.42 956.69,1161.42 968.51,1161.42 1051.18,1161.42 U1.AA2@1070.87,1181.1
  Bottom Layer w7.87: v2(114.17,1236.22) HDR_L.65@173.23,1236.22
EXTEND_A33: HDR_L.67 U1.AB2 | length 1094
  Top Layer w5: v2(114.17,1204.72) 177.16,1204.73 291.34,1090.55 507.87,1090.55 515.75,1098.43 732.28,1098.43 744.09,1086.62 913.39,1086.62 948.82,1122.05 956.69,1122.05 968.5,1122.05 1051.18,1122.05 U1.AB2@1070.87,1141.73
  Bottom Layer w7.87: v2(114.17,1204.72) HDR_L.67@173.23,1204.72
EXTEND_A34: HDR_L.69 U1.AC2 | length 1100.5
  Top Layer w5: v2(114.17,1173.23) 177.16,1173.23 283.46,1066.93 507.87,1066.93 515.75,1059.05 562.99,1059.05 586.61,1035.43 716.54,1035.43 736.22,1055.12 917.32,1055.12 944.88,1082.68 956.69,1082.68 968.51,1082.68 1051.18,1082.68 U1.AC2@1070.87,1102.36
  Bottom Layer w7.87: v2(114.17,1173.23) HDR_L.69@173.23,1173.23
EXTEND_A35: HDR_L.71 U1.P6 | length 1326.5
  Top Layer w7.87: v1(1208.66,1437.01) U1.P6@1228.35,1456.69
  MidLayer2 w5: v2(114.17,1141.73) 145.67,1141.73 448.81,1444.88 507.87,1444.88 519.68,1433.07 909.45,1433.07 925.2,1417.32 956.69,1417.32 968.51,1417.32 1188.98,1417.32 v1(1208.66,1437.01)
  Bottom Layer w7.87: v2(114.17,1141.73) HDR_L.71@173.23,1141.73
EXTEND_A36: HDR_L.73 U1.R6 | length 1333
  Top Layer w7.87: v1(1208.66,1397.64) U1.R6@1228.35,1417.32
  MidLayer2 w5: v2(114.17,1110.24) 145.67,1110.24 440.94,1405.51 507.87,1405.51 519.69,1417.32 874.02,1417.32 913.39,1377.95 956.69,1377.95 968.51,1377.95 1188.98,1377.95 v1(1208.66,1397.64)
  Bottom Layer w7.87: v2(114.17,1110.24) HDR_L.73@173.23,1110.23
EXTEND_A37: HDR_L.75 U1.T6 | length 1333
  Top Layer w7.87: v1(1208.66,1358.27) U1.T6@1228.35,1377.95
  MidLayer2 w5: v2(114.17,1078.74) 145.67,1078.74 448.81,1381.89 507.87,1381.89 519.68,1370.08 877.95,1370.08 909.45,1338.58 956.69,1338.58 968.51,1338.58 1188.98,1338.58 v1(1208.66,1358.27)
  Bottom Layer w7.87: v2(114.17,1078.74) HDR_L.75@173.23,1078.74
EXTEND_A38: HDR_L.77 U1.U5 | length 1300.2
  Top Layer w7.87: v1(1169.29,1318.9) U1.U5@1188.98,1338.58
  MidLayer2 w5: v2(114.17,1047.24) 145.67,1047.24 440.94,1342.52 507.87,1342.52 519.69,1354.33 874.02,1354.33 929.13,1299.21 956.69,1299.21 968.5,1299.21 1149.61,1299.21 v1(1169.29,1318.9)
  Bottom Layer w7.87: v2(114.17,1047.24) HDR_L.77@173.23,1047.24
EXTEND_A39: HDR_L.79 U1.W7 | length 1378.9
  Top Layer w7.87: v1(1248.03,1240.16) U1.W7@1267.72,1259.84
  MidLayer2 w5: v2(114.17,1015.75) 145.67,1015.75 448.81,1318.9 507.87,1318.9 519.68,1307.09 901.58,1307.09 948.82,1259.84 956.69,1259.84 968.5,1259.84 1228.34,1259.84 v1(1248.03,1240.16)
  Bottom Layer w7.87: v2(114.17,1015.75) HDR_L.79@173.23,1015.74
EXTEND_A40: HDR_L.81 U1.W6 | length 1346.1
  Top Layer w7.87: v1(1208.66,1240.16) U1.W6@1228.35,1259.84
  MidLayer2 w5: v2(114.17,984.25) 145.67,984.25 440.94,1279.53 507.87,1279.53 519.69,1291.34 814.96,1291.34 885.83,1220.47 956.69,1220.47 968.5,1220.47 1188.97,1220.47 v1(1208.66,1240.16)
  Bottom Layer w7.87: v2(114.17,984.25) HDR_L.81@173.23,984.25
EXTEND_A41: HDR_L.83 U1.Y5 | length 1306.7
  Top Layer w7.87: v1(1169.29,1200.79) U1.Y5@1188.98,1220.47
  MidLayer2 w5: v2(114.17,952.76) 145.67,952.75 448.81,1255.9 507.87,1255.9 519.69,1244.09 842.52,1244.09 905.51,1181.1 956.69,1181.1 968.5,1181.1 1149.61,1181.1 v1(1169.29,1200.79)
  Bottom Layer w7.87: v2(114.17,952.76) HDR_L.83@173.23,952.75
EXTEND_A42: HDR_L.85 U1.AA5 | length 1313.2
  Top Layer w7.87: v1(1169.29,1161.42) U1.AA5@1188.98,1181.1
  MidLayer2 w5: v2(114.17,921.26) 145.67,921.26 440.94,1216.53 507.87,1216.53 519.69,1228.34 838.58,1228.34 925.2,1141.73 956.69,1141.73 968.5,1141.73 1149.61,1141.73 v1(1169.29,1161.42)
  Bottom Layer w7.87: v2(114.17,921.26) HDR_L.85@173.23,921.26
EXTEND_A43: HDR_L.87 U1.AA6 | length 1385.1
  Top Layer w7.87: v1(1208.66,1161.42) U1.AA6@1228.35,1181.1
  MidLayer2 w5: v2(114.17,889.76) 145.67,889.76 448.81,1192.91 507.87,1192.91 519.69,1181.1 866.14,1181.1 944.88,1102.36 956.69,1102.36 968.5,1102.36 1177.17,1102.36 1188.98,1114.17 1188.98,1141.73 v1(1208.66,1161.42)
  Bottom Layer w7.87: v2(114.17,889.76) HDR_L.87@173.23,889.76
EXTEND_A44: HDR_L.89 U1.T5 | length 1349.1
  Top Layer w7.87: v1(1169.29,1358.27) U1.T5@1188.98,1377.95
  MidLayer3 w5: v2(114.17,858.27) 149.61,858.27 629.92,1338.58 956.69,1338.58 968.5,1338.58 1149.61,1338.58 v1(1169.29,1358.27)
  Bottom Layer w7.87: v2(114.17,858.27) HDR_L.89@173.23,858.26
EXTEND_A45: HDR_L.91 U1.W5 | length 1313.2
  Top Layer w7.87: v1(1169.29,1240.16) U1.W5@1188.98,1259.84
  MidLayer3 w5: v2(114.17,826.77) 181.1,826.77 574.8,1220.47 956.69,1220.47 968.5,1220.47 1149.61,1220.47 v1(1169.29,1240.16)
  Bottom Layer w7.87: v2(114.17,826.77) HDR_L.91@173.23,826.77
EXTEND_A46: HDR_L.93 U1.Y6 | length 1349.4
  Top Layer w7.87: v1(1208.66,1200.79) U1.Y6@1228.35,1220.47
  MidLayer3 w5: v2(114.17,795.28) 212.6,795.28 598.43,1181.1 956.69,1181.1 968.5,1181.1 1188.98,1181.1 v1(1208.66,1200.79)
  Bottom Layer w7.87: v2(114.17,795.28) HDR_L.93@173.23,795.27
EXTEND_A47: HDR_L.95 U1.AB6 | length 1346.1
  Top Layer w7.87: v1(1208.66,1122.05) U1.AB6@1228.35,1141.73
  MidLayer3 w5: v2(114.17,763.78) 244.09,763.78 622.05,1141.73 956.69,1141.73 968.5,1141.73 1188.97,1141.73 v1(1208.66,1122.05)
  Bottom Layer w7.87: v2(114.17,763.78) HDR_L.95@173.23,763.78
EXTEND_A48: HDR_L.97 U1.AB5 | length 1324.2
  Top Layer w7.87: v1(1169.29,1122.05) U1.AB5@1188.98,1141.73
  MidLayer3 w5: v2(114.17,732.28) 275.59,732.28 556.59,1013.28 556.59,1048.72 590.55,1082.68 625.98,1082.68 913.39,1082.68 933.07,1102.36 956.69,1102.36 968.5,1102.36 1149.61,1102.36 v1(1169.29,1122.05)
  Bottom Layer w7.87: v2(114.17,732.28) HDR_L.97@173.23,732.28
EXTEND_A49: HDR_L.99 U1.AC4 | length 1260.8
  Top Layer w7.87: v1(1129.92,1082.68) U1.AC4@1149.61,1102.36
  MidLayer3 w5: v2(114.17,700.79) 307.09,700.79 633.86,1027.56 811.02,1027.56 846.46,1062.99 956.69,1062.99 968.5,1062.99 1110.24,1062.99 v1(1129.92,1082.68)
  Bottom Layer w7.87: v2(114.17,700.79) HDR_L.99@173.23,700.78
EXTEND_B0: HDR_L.2 U1.C3 | length 816.1
  Top Layer w7.87: v1(1090.55,1909.45) U1.C3@1110.24,1889.76
  MidLayer1 w5: v2(500,2244.1) 523.62,2244.1 758.99,2008.73 829.85,2008.73 929.13,1909.45 956.69,1909.45 968.5,1909.45 v1(1090.55,1909.45)
  Bottom Layer w7.87: HDR_L.2@440.94,2244.09 v2(500,2244.1)
EXTEND_B1: HDR_L.4 U1.D3 | length 819.3
  Top Layer w7.87: v1(1090.55,1870.08) U1.D3@1110.24,1850.39
  MidLayer1 w5: v2(523.62,2212.6) 772.4,1963.82 789.18,1947.04 815.41,1947.04 892.37,1870.08 956.69,1870.08 968.5,1870.08 v1@1090.55,1870.08
  Bottom Layer w7.87: HDR_L.4@440.94,2212.6 v2(523.62,2212.6)
EXTEND_B2: HDR_L.6 U1.E5 | length 969.2
  Top Layer w7.87: v1@1169.28,1826.78 U1.E5@1188.97,1807.09 ; v1(1169.29,1830.71) U1.E5@1188.98,1811.02 v1(1169.29,1830.71)
  MidLayer1 w5: v2(500,2181.1) 523.62,2181.1 768.09,1936.63 768.09,1926.37 844.07,1850.39 956.69,1850.39 968.5,1850.39 1149.61,1850.39 v1(1169.29,1830.71) ; v1@1167.32,1828.74 1169.68,1829.53 v1@1173.23,1830.71
  Bottom Layer w7.87: HDR_L.6@440.94,2181.1 v2(500,2181.1)
EXTEND_B3: HDR_L.8 U1.E3 | length 809.5
  Top Layer w7.87: v1(1090.55,1830.71) U1.E3@1110.24,1811.02
  MidLayer1 w5: v2(523.62,2149.61) 834.65,1838.58 929.13,1838.58 937.01,1830.71 956.69,1830.71 968.5,1830.71 v1(1090.55,1830.71)
  Bottom Layer w7.87: HDR_L.8@440.94,2149.6 v2(523.62,2149.61)
EXTEND_B4: HDR_L.10 U1.F4 | length 852.2
  Top Layer w7.87: v1(1129.92,1791.34) U1.F4@1149.61,1771.65
  MidLayer1 w5: v2(500,2118.11) 523.62,2118.11 818.9,1822.83 917.32,1822.83 929.13,1811.02 956.69,1811.02 968.5,1811.02 1110.24,1811.02 v1(1129.92,1791.34)
  Bottom Layer w7.87: HDR_L.10@440.94,2118.11 v2(500,2118.11)
EXTEND_B5: HDR_L.12 U1.F3 | length 812.8
  Top Layer w7.87: v1(1090.55,1791.34) U1.F3@1110.24,1771.65
  MidLayer1 w5: v2(523.62,2086.62) 834.65,1775.59 917.32,1775.59 933.07,1791.34 956.69,1791.34 968.5,1791.34 v1@1090.55,1791.34
  Bottom Layer w7.87: HDR_L.12@440.94,2086.61 v2(523.62,2086.62)
EXTEND_B6: HDR_L.14 U1.G4 | length 848.9
  Top Layer w7.87: v1(1129.92,1751.97) U1.G4@1149.61,1732.28
  MidLayer1 w5: v2(500,2055.12) 523.62,2055.12 814.96,1763.78 937.01,1763.78 944.88,1771.65 956.69,1771.65 968.5,1771.65 1110.24,1771.65 v1(1129.92,1751.97)
  Bottom Layer w7.87: HDR_L.14@440.94,2055.12 v2(500,2055.12)
EXTEND_B7: HDR_L.16 U1.G3 | length 790
  Top Layer w7.87: v1(1090.55,1751.97) U1.G3@1110.24,1732.28
  MidLayer1 w5: v2(523.62,2023.62) 795.28,1751.97 956.69,1751.97 968.5,1751.97 v1@1090.55,1751.97
  Bottom Layer w7.87: HDR_L.16@440.94,2023.62 v2(523.62,2023.62)
EXTEND_B8: HDR_L.18 U1.H4 | length 832.6
  Top Layer w7.87: v1(1129.92,1712.6) U1.H4@1149.61,1692.91
  MidLayer1 w5: v2(500,1992.13) 523.62,1992.13 783.47,1732.28 956.69,1732.28 968.5,1732.28 1110.24,1732.28 v1(1129.92,1712.6)
  Bottom Layer w7.87: HDR_L.18@440.94,1992.12 v2(500,1992.13)
EXTEND_B9: HDR_L.20 U1.H3 | length 780.2
  Top Layer w7.87: v1(1090.55,1712.6) U1.H3@1110.24,1692.91
  MidLayer1 w5: v2(523.62,1960.63) 771.66,1712.6 956.69,1712.6 968.5,1712.6 v1@1090.55,1712.6
  Bottom Layer w7.87: HDR_L.20@440.94,1960.63 v2(523.62,1960.63)
EXTEND_B10: HDR_L.22 U1.J4 | length 822.8
  Top Layer w7.87: v1(1129.92,1673.23) U1.J4@1149.61,1653.54
  MidLayer1 w5: v2(500,1929.14) 523.62,1929.14 759.84,1692.91 956.69,1692.91 968.5,1692.91 1110.24,1692.91 v1(1129.92,1673.23)
  Bottom Layer w7.87: HDR_L.22@440.94,1929.13 v2(500,1929.14)
EXTEND_B11: HDR_L.24 U1.J3 | length 770.4
  Top Layer w7.87: v1(1090.55,1673.23) U1.J3@1110.24,1653.54
  MidLayer1 w5: v2(523.62,1897.64) 740.16,1681.1 956.69,1681.1 968.51,1681.1 1059.06,1681.1 1066.93,1673.23 v1@1090.55,1673.23
  Bottom Layer w7.87: HDR_L.24@440.94,1897.64 v2(523.62,1897.64)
